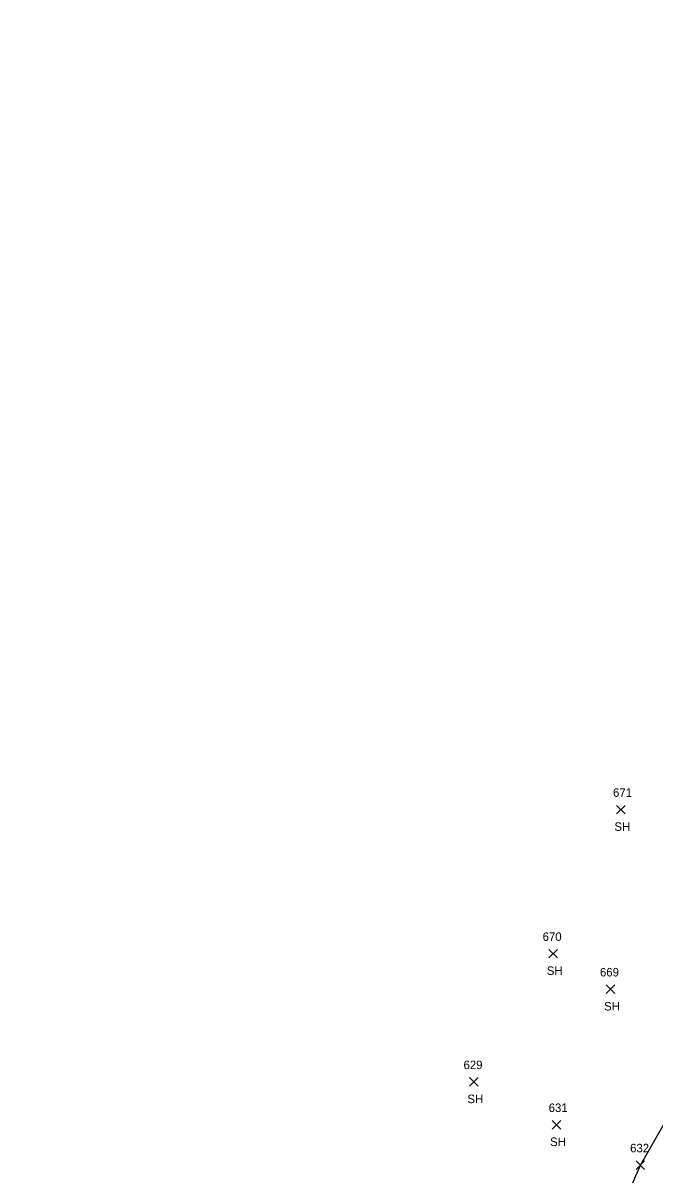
# Model space of a CAD drawing. Extents: x 1586965 to 1590952, y 716317 to 720029.
# Drawn here: x 1586974.2 to 1587122.8, y 719388.4 to 719659.2 of the extents above; entities that cross this region are included whole.
import ezdxf

# ---------------------------------------------------------------- set-up
doc = ezdxf.new("R2010")
doc.units = 0
for name, color, linetype in [('L_A', 7, 'Continuous'), ('L_I', 7, 'Continuous'), ('L_TIC', 7, 'Continuous'), ('LELB', 7, 'Continuous')]:
    doc.layers.add(name, color=color, linetype=linetype)

msp = doc.modelspace()

# ---------------------------------------------------------------- linework, layer by layer
at = {"layer": 'L_TIC'}
for points in [[(1587113.77, 719473.32), (1587115.77, 719475.32)], [(1587115.77, 719473.32), (1587113.77, 719475.32)], [(1587097.87, 719439.45), (1587099.87, 719441.45)], [(1587099.87, 719439.45), (1587097.87, 719441.45)], [(1587111.33, 719431.1), (1587113.33, 719433.1)], [(1587113.33, 719431.1), (1587111.33, 719433.1)], [(1587079.2, 719409.31), (1587081.2, 719411.31)], [(1587081.2, 719409.31), (1587079.2, 719411.31)], [(1587098.64, 719399.23), (1587100.64, 719401.23)], [(1587100.64, 719399.23), (1587098.64, 719401.23)], [(1587118.36, 719389.75), (1587120.36, 719391.75)], [(1587120.36, 719389.75), (1587118.36, 719391.75)]]:
    msp.add_lwpolyline(points, dxfattribs=at)
at = {"layer": 'LELB'}
msp.add_lwpolyline([(1586974.22, 719201.38), (1587004.64, 719224.97), (1587038.23, 719264.63), (1587070.35, 719308.83), (1587101.6, 719349.88), (1587119.36, 719390.75), (1587135.94, 719419.64), (1587149.18, 719457.32), (1587161.88, 719497.01), (1587171.82, 719537.32), (1587183.93, 719559.95), (1587196.31, 719595.67), (1587210.79, 719616.33), (1587226.54, 719644.19), (1587252.78, 719668.03), (1587275.41, 719699.75), (1587291.25, 719715.32), (1587307.92, 719729.13), (1587319.25, 719735.05), (1587320, 719753.34), (1587323.07, 719768.88), (1587320.57, 719781.92), (1587330.74, 719804.48), (1587340.87, 719823.38)], dxfattribs=at)
msp.add_lwpolyline([(1586974.22, 719201.38), (1587004.64, 719224.97), (1587038.23, 719264.63), (1587070.35, 719308.83), (1587101.6, 719349.88), (1587119.36, 719390.75), (1587135.94, 719419.64), (1587149.18, 719457.32), (1587161.88, 719497.01), (1587171.82, 719537.32), (1587183.93, 719559.95), (1587196.31, 719595.67), (1587210.79, 719616.33), (1587226.54, 719644.19), (1587252.78, 719668.03), (1587275.41, 719699.75), (1587291.25, 719715.32), (1587307.92, 719729.13), (1587319.25, 719735.05), (1587320, 719753.34), (1587323.07, 719768.88), (1587320.57, 719781.92), (1587330.74, 719804.48), (1587340.87, 719823.38)], dxfattribs=at)

# ---------------------------------------------------------------- texts
at = {"layer": 'L_A'}
for p in [(1587113.26, 719469.32), (1587097.36, 719435.45), (1587110.81, 719427.1), (1587078.69, 719405.31), (1587098.13, 719395.23)]:
    msp.add_text('SH', height=2, dxfattribs=at).set_placement(p)
at = {"layer": 'L_I'}
for s, p in [('671', (1587112.93, 719477.32)), ('670', (1587096.38, 719443.45)), ('669', (1587109.86, 719435.1)), ('629', (1587077.78, 719413.31)), ('631', (1587097.8, 719403.23)), ('632', (1587116.95, 719393.75))]:
    msp.add_text(s, height=2, dxfattribs=at).set_placement(p)

doc.saveas('drawing.dxf')
